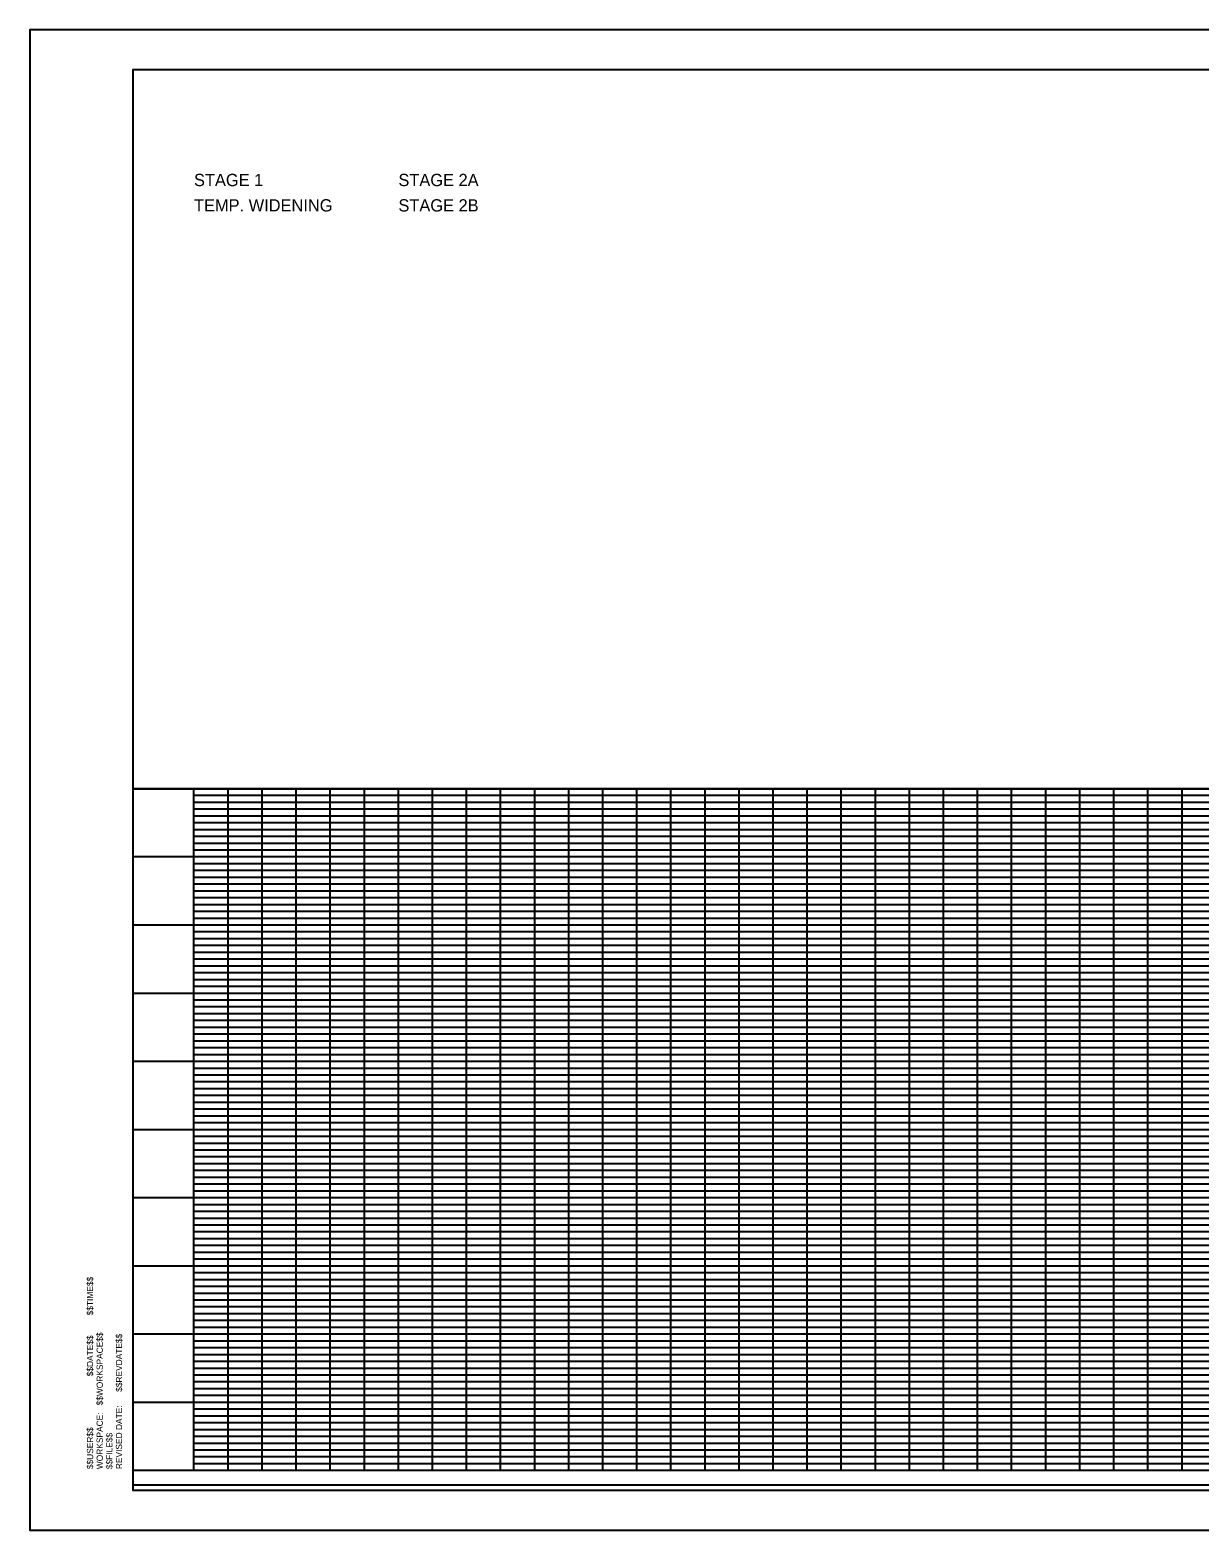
# Model space of a CAD drawing. Extents: x 0 to 1228740, y 0 to 152440.
# Drawn here: x 0 to 17.16, y 0 to 22 of the extents above; entities that cross this region are included whole.
import ezdxf

# ---------------------------------------------------------------- set-up
doc = ezdxf.new("R2010")
doc.units = 0
for name, color, linetype in [('G-TBLK', 7, 'Continuous'), ('R_Border', 7, 'Continuous'), ('R_Grid', 7, 'Continuous'), ('R_No Plot', 7, 'Continuous'), ('R_XS_EARTHWORK_STAGE1', 7, 'Continuous'), ('R_XS_EARTHWORK_STAGE2', 7, 'Continuous')]:
    doc.layers.add(name, color=color, linetype=linetype)

msp = doc.modelspace()

# ---------------------------------------------------------------- linework, layer by layer
at = {"layer": 'R_Border'}
for p, q in [((1.516, 21.423), (33.423, 21.423)), ((1.516, 0.577), (1.516, 21.423)), ((33.423, 0.577), (1.516, 0.577))]:
    msp.add_line(p, q, dxfattribs=at)
msp.add_lwpolyline([(34, 22), (0, 22), (0, 0), (34, 0)], close=True, dxfattribs=at)
at = {"layer": 'R_Grid'}
for p, q in [((33.423, 10.871), (1.516, 10.871)), ((2.407, 0.871), (2.407, 10.871)), ((2.907, 0.871), (2.907, 10.871)), ((3.407, 0.871), (3.407, 10.871)), ((3.907, 0.871), (3.907, 10.871)), ((4.407, 0.871), (4.407, 10.871)), ((4.907, 0.871), (4.907, 10.871)), ((5.407, 0.871), (5.407, 10.871)), ((5.907, 0.871), (5.907, 10.871)), ((6.407, 0.871), (6.407, 10.871)), ((6.907, 0.871), (6.907, 10.871)), ((7.407, 0.871), (7.407, 10.871)), ((7.907, 0.871), (7.907, 10.871)), ((8.407, 0.871), (8.407, 10.871)), ((8.907, 0.871), (8.907, 10.871)), ((9.407, 0.871), (9.407, 10.871)), ((9.907, 0.871), (9.907, 10.871)), ((10.407, 0.871), (10.407, 10.871)), ((10.907, 0.871), (10.907, 10.871)), ((11.407, 0.871), (11.407, 10.871)), ((11.907, 0.871), (11.907, 10.871)), ((12.407, 0.871), (12.407, 10.871)), ((12.907, 0.871), (12.907, 10.871)), ((13.407, 0.871), (13.407, 10.871)), ((13.907, 0.871), (13.907, 10.871)), ((14.407, 0.871), (14.407, 10.871)), ((14.907, 0.871), (14.907, 10.871)), ((15.407, 0.871), (15.407, 10.871)), ((15.907, 0.871), (15.907, 10.871)), ((16.407, 0.871), (16.407, 10.871)), ((16.907, 0.871), (16.907, 10.871)), ((32.407, 10.771), (2.407, 10.771)), ((32.407, 10.671), (2.407, 10.671)), ((32.407, 10.571), (2.407, 10.571)), ((32.407, 10.471), (2.407, 10.471)), ((32.407, 10.371), (2.407, 10.371)), ((32.407, 10.271), (2.407, 10.271)), ((32.407, 10.171), (2.407, 10.171)), ((32.407, 10.071), (2.407, 10.071)), ((32.407, 9.971), (2.407, 9.971)), ((33.423, 9.871), (1.516, 9.871)), ((32.407, 9.771), (2.407, 9.771)), ((32.407, 9.671), (2.407, 9.671)), ((32.407, 9.571), (2.407, 9.571)), ((32.407, 9.471), (2.407, 9.471)), ((32.407, 9.371), (2.407, 9.371)), ((32.407, 9.271), (2.407, 9.271)), ((32.407, 9.171), (2.407, 9.171)), ((32.407, 9.071), (2.407, 9.071)), ((33.423, 8.871), (1.516, 8.871)), ((32.407, 8.971), (2.407, 8.971)), ((32.407, 8.771), (2.407, 8.771)), ((32.407, 8.671), (2.407, 8.671)), ((32.407, 8.571), (2.407, 8.571)), ((32.407, 8.471), (2.407, 8.471)), ((32.407, 8.371), (2.407, 8.371)), ((32.407, 8.271), (2.407, 8.271)), ((32.407, 8.171), (2.407, 8.171)), ((32.407, 8.071), (2.407, 8.071)), ((32.407, 7.971), (2.407, 7.971)), ((33.423, 7.871), (1.516, 7.871)), ((32.407, 7.771), (2.407, 7.771)), ((32.407, 7.671), (2.407, 7.671)), ((32.407, 7.571), (2.407, 7.571)), ((32.407, 7.471), (2.407, 7.471)), ((32.407, 7.371), (2.407, 7.371)), ((32.407, 7.271), (2.407, 7.271)), ((32.407, 7.171), (2.407, 7.171)), ((32.407, 7.071), (2.407, 7.071)), ((33.423, 6.871), (1.516, 6.871)), ((32.407, 6.971), (2.407, 6.971)), ((32.407, 6.771), (2.407, 6.771)), ((32.407, 6.671), (2.407, 6.671)), ((32.407, 6.571), (2.407, 6.571)), ((32.407, 6.471), (2.407, 6.471)), ((32.407, 6.371), (2.407, 6.371)), ((32.407, 6.271), (2.407, 6.271)), ((32.407, 6.171), (2.407, 6.171)), ((32.407, 6.071), (2.407, 6.071)), ((32.407, 5.971), (2.407, 5.971)), ((33.423, 5.871), (1.516, 5.871)), ((32.407, 5.771), (2.407, 5.771)), ((32.407, 5.671), (2.407, 5.671)), ((32.407, 5.571), (2.407, 5.571)), ((32.407, 5.471), (2.407, 5.471)), ((32.407, 5.371), (2.407, 5.371)), ((32.407, 5.271), (2.407, 5.271)), ((32.407, 5.171), (2.407, 5.171)), ((32.407, 5.071), (2.407, 5.071)), ((33.423, 4.871), (1.516, 4.871)), ((32.407, 4.971), (2.407, 4.971)), ((32.407, 4.771), (2.407, 4.771)), ((32.407, 4.671), (2.407, 4.671)), ((32.407, 4.571), (2.407, 4.571)), ((32.407, 4.471), (2.407, 4.471)), ((32.407, 4.371), (2.407, 4.371)), ((32.407, 4.271), (2.407, 4.271)), ((32.407, 4.171), (2.407, 4.171)), ((32.407, 4.071), (2.407, 4.071)), ((32.407, 3.971), (2.407, 3.971)), ((33.423, 3.871), (1.516, 3.871)), ((32.407, 3.771), (2.407, 3.771)), ((32.407, 3.671), (2.407, 3.671)), ((32.407, 3.571), (2.407, 3.571)), ((32.407, 3.471), (2.407, 3.471)), ((32.407, 3.371), (2.407, 3.371)), ((32.407, 3.271), (2.407, 3.271)), ((32.407, 3.171), (2.407, 3.171)), ((33.423, 2.871), (1.516, 2.871)), ((32.407, 3.071), (2.407, 3.071)), ((32.407, 2.971), (2.407, 2.971)), ((32.407, 2.771), (2.407, 2.771)), ((32.407, 2.671), (2.407, 2.671)), ((32.407, 2.571), (2.407, 2.571)), ((32.407, 2.471), (2.407, 2.471)), ((32.407, 2.371), (2.407, 2.371)), ((32.407, 2.271), (2.407, 2.271)), ((32.407, 2.171), (2.407, 2.171)), ((32.407, 2.071), (2.407, 2.071)), ((33.423, 1.871), (1.516, 1.871)), ((32.407, 1.971), (2.407, 1.971)), ((32.407, 1.771), (2.407, 1.771)), ((32.407, 1.671), (2.407, 1.671)), ((32.407, 1.571), (2.407, 1.571)), ((32.407, 1.471), (2.407, 1.471)), ((32.407, 1.371), (2.407, 1.371)), ((32.407, 1.271), (2.407, 1.271)), ((32.407, 1.171), (2.407, 1.171)), ((32.407, 1.071), (2.407, 1.071)), ((32.407, 0.971), (2.407, 0.971)), ((33.423, 0.871), (1.516, 0.871))]:
    msp.add_line(p, q, dxfattribs=at)
at = {"layer": 'R_No Plot'}
for points in [[(33.423, 17.405), (33.423, 10.871), (1.516, 10.871), (1.516, 21.423), (25.197, 21.423), (25.197, 20.435), (28.749, 20.435), (28.749, 20.078), (29.113, 20.078), (29.113, 20.143), (30.667, 20.143)], [(33.423, 17.405), (33.423, 0.657), (1.516, 0.657), (1.516, 21.423), (25.197, 21.423), (25.197, 20.435), (28.749, 20.435), (28.749, 20.078), (29.113, 20.078), (29.113, 20.143), (30.667, 20.143)]]:
    msp.add_lwpolyline(points, dxfattribs=at)
msp.add_lwpolyline([(1.516, 10.871), (33.423, 10.871), (33.423, 0.577), (1.516, 0.577)], close=True, dxfattribs=at)

# ---------------------------------------------------------------- texts
at = {"layer": 'G-TBLK'}
for s, p in [('$$TIME$$', (0.927, 3.148)), ('$$WORKSPACE$$', (1.069, 1.827)), ('$$REVDATE$$', (1.352, 2.026)), ('$$DATE$$', (0.927, 2.254)), ('REVISED DATE:', (1.352, 0.893)), ('WORKSPACE:', (1.069, 0.892)), ('$$USER$$', (0.927, 0.892)), ('$$FILE$$', (1.211, 0.892))]:
    msp.add_text(s, height=0.0918, rotation=90, dxfattribs=at).set_placement(p)
at = {"layer": 'R_XS_EARTHWORK_STAGE1'}
for s, p in [('STAGE 1', (2.407, 19.71)), ('TEMP. WIDENING', (2.407, 19.338))]:
    msp.add_text(s, height=0.18, dxfattribs=at).set_placement(p)
at = {"layer": 'R_XS_EARTHWORK_STAGE2'}
for s, p in [('STAGE 2A', (5.407, 19.71)), ('STAGE 2B', (5.407, 19.338))]:
    msp.add_text(s, height=0.18, dxfattribs=at).set_placement(p)

doc.saveas('drawing.dxf')
